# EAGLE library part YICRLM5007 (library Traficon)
LM5007
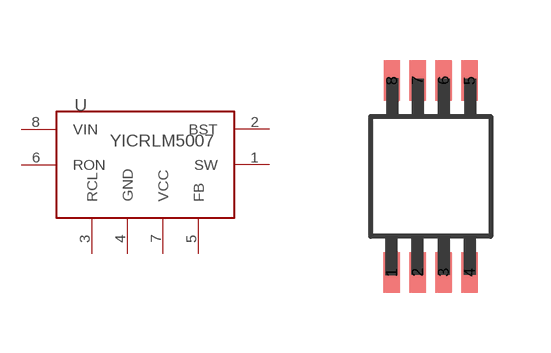
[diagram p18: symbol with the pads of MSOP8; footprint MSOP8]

Designator prefix U

## YICRLM5007  [MSOP8]
1  SW  out
2  BST  out
3  RCL  in
4  GND  in
5  FB  in
6  RON  in
7  VCC  in
8  VIN  in

## Footprint MSOP8 (pad centres in mm)
smd 0.41 x 1.02: 1 -0.975,-2.4; 2 -0.325,-2.4; 3 0.325,-2.4; 4 0.975,-2.4; 5 0.975,2.4; 6 0.325,2.4; 7 -0.325,2.4; 8 -0.97,2.4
